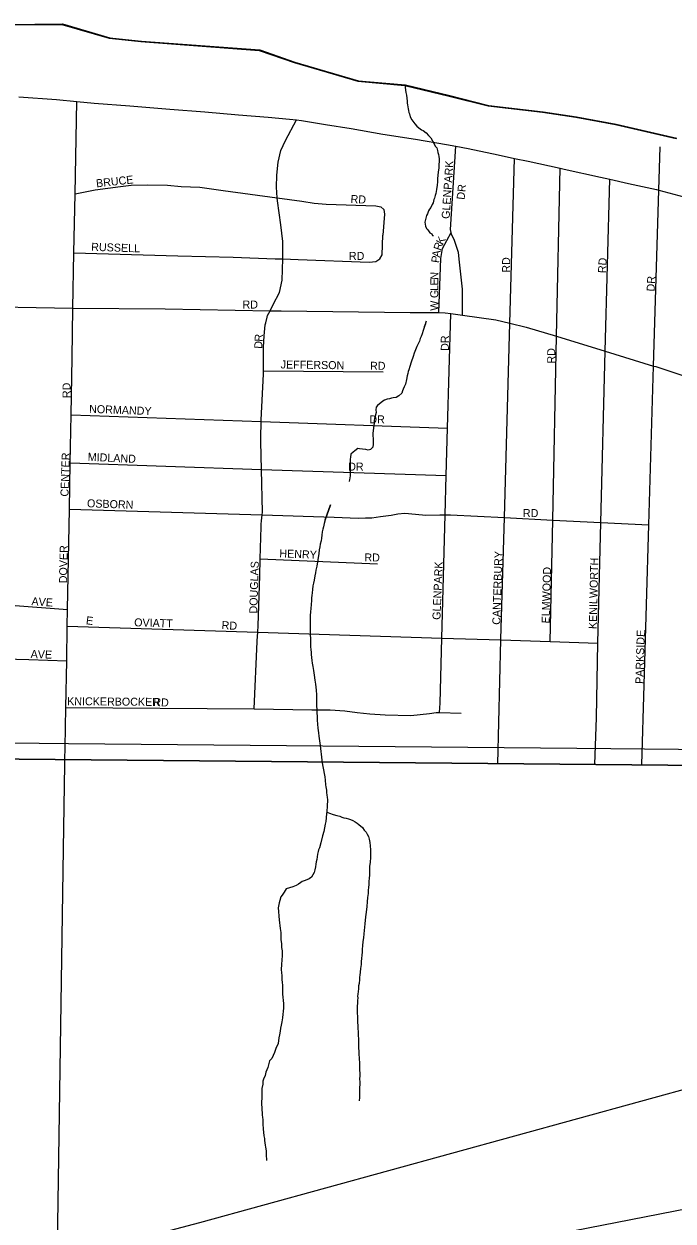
# Model space of a CAD drawing. Extents: x 2010165 to 2382125, y 1060529 to 1407316.
# Drawn here: x 2126953 to 2131007, y 1264406 to 1271883 of the extents above; entities that cross this region are included whole.
import ezdxf

# ---------------------------------------------------------------- set-up
doc = ezdxf.new("R2010")
doc.units = 0
for name, color, linetype in [('GM_X_City_Street', 7, 'Continuous'), ('GM_X_City_Street_Text', 7, 'Continuous'), ('GM_X_Corporation', 7, 'Continuous'), ('GM_X_County', 7, 'Continuous'), ('GM_X_Interstate_Route', 7, 'Continuous'), ('GM_X_Major_Lake', 7, 'Continuous'), ('GM_X_Major_River', 7, 'Continuous'), ('GM_X_Minor_River', 7, 'Continuous'), ('GM_X_Rail_Line', 7, 'Continuous'), ('GM_X_State_Route', 7, 'Continuous'), ('GM_X_US_Route', 7, 'Continuous')]:
    doc.layers.add(name, color=color, linetype=linetype)

msp = doc.modelspace()

# ---------------------------------------------------------------- linework, layer by layer
at = {"layer": 'GM_X_City_Street'}
for points in [[(2127210.5, 1267364.4), (2127214.9, 1267613.4), (2127220.1, 1267906), (2127224, 1268122.6), (2127225.8, 1268226.8), (2127237, 1268852.4), (2127242.1, 1269141.1), (2127247.5, 1269441.7), (2127253.8, 1269797.9), (2127259.3, 1270107.5), (2127265.6, 1270454.1), (2127272.4, 1270822), (2127283, 1271398.9)], [(2128462.9, 1270016.9), (2128471.6, 1270052.2), (2128474, 1270061.9), (2128490.2, 1270092.1), (2128510.3, 1270129.9), (2128548.7, 1270206), (2128565.1, 1270282.1), (2128569.2, 1270415.2), (2128569.8, 1270434.4), (2128570.2, 1270524.7), (2128556.7, 1270629), (2128537.3, 1270777.4), (2128535.6, 1270797.1), (2128529.7, 1270863.6), (2128532.1, 1270937.8), (2128540.4, 1271020), (2128556.8, 1271092.1), (2128587.1, 1271156.1), (2128655.5, 1271283.4)], [(2129693.1, 1270064.2), (2129692, 1270227.3), (2129672.7, 1270395.8), (2129667, 1270456), (2129643.3, 1270530.3), (2129623.5, 1270570.4), (2129621.5, 1270579.9), (2129617.6, 1270598.5), (2129650.6, 1271119.3)], [(2130813, 1267255.1), (2130856.4, 1268754.9), (2130886.2, 1269746.7), (2130919.1, 1270844.6), (2130927.3, 1271116.4)], [(2129912.6, 1267261.2), (2129932.1, 1268035.8), (2129932.2, 1268041), (2129953.6, 1268799.6), (2129987.8, 1270014), (2130016.8, 1271043.6)], [(2130240.3, 1268025.9), (2130256.1, 1268784.6), (2130280.1, 1269932.3), (2130302, 1270982.5)], [(2127272.4, 1270822), (2127397.9, 1270846.9), (2127556.1, 1270868.7), (2127622.2, 1270875.3), (2127726.4, 1270878.4), (2127850.7, 1270875.7), (2127935, 1270868.6), (2128051.3, 1270863.7), (2128197.8, 1270843.2), (2128535.6, 1270797.1), (2128689.6, 1270776), (2128765.9, 1270764.7), (2128840.2, 1270757.5), (2129151, 1270746.7), (2129183.1, 1270741), (2129201.3, 1270725.1), (2129205.6, 1270695.1), (2129195, 1270564.2)], [(2130518.7, 1267257.9), (2130528.6, 1267551.3), (2130536.7, 1268016.4), (2130556.2, 1268769.8), (2130583.9, 1269839.2), (2130611.7, 1270913.6)], [(2127265.6, 1270454.1), (2127915.1, 1270435.1), (2128259.5, 1270425.7), (2128522.7, 1270416.8), (2128569.2, 1270415.2), (2128665.8, 1270412), (2129110.1, 1270396.1), (2129150.2, 1270400), (2129176.3, 1270415.9), (2129190.4, 1270441.9), (2129195, 1270564.2)], [(2129545.1, 1270080.3), (2129552.2, 1270306.1), (2129556.7, 1270418.3), (2129567, 1270480.4), (2129621.5, 1270579.9)], [(2126064.8, 1270130.3), (2126571.4, 1270120.6), (2127259.3, 1270107.5)], [(2127259.3, 1270107.5), (2127835.5, 1270104.1), (2128490.2, 1270092.1), (2128559.8, 1270090.9), (2129366.2, 1270081.7), (2129545.1, 1270080.3), (2129584.3, 1270079.9), (2129618.9, 1270075), (2129693.1, 1270064.2), (2129900.4, 1270034.2), (2129987.8, 1270014), (2130090.6, 1269990.3), (2130280.1, 1269932.3), (2130583.9, 1269839.2), (2130886.2, 1269746.7), (2130899.1, 1269742.7), (2131245.9, 1269629.5)], [(2129547.8, 1267583), (2129552, 1267641.6), (2129563.2, 1268047.6), (2129584.3, 1268816.3), (2129591.1, 1269062.8), (2129599.2, 1269359.5), (2129618.9, 1270075)], [(2128433.5, 1269336.2), (2128434.1, 1269363.3), (2128434.8, 1269400.2), (2128435, 1269410.5), (2128450.3, 1269695.1), (2128450.1, 1269717.2), (2128449.1, 1269863.5), (2128453.4, 1269935.7), (2128459.7, 1270003.9), (2128462.9, 1270016.9)], [(2128450.1, 1269717.2), (2129197.1, 1269710.1)], [(2127247.5, 1269441.7), (2128434.8, 1269400.2), (2129599.2, 1269359.5)], [(2128435.5, 1268759.6), (2128437.4, 1268780), (2128440.8, 1268816.5), (2128442.4, 1268833.1), (2128436.3, 1269101.3), (2128432.4, 1269274.2), (2128433.5, 1269336.2)], [(2127242.1, 1269141.1), (2128436.3, 1269101.3), (2129591.1, 1269062.8)], [(2127237, 1268852.4), (2128440.8, 1268816.5), (2128890.7, 1268803.1), (2129040.8, 1268796.5), (2129086.9, 1268798.3), (2129126.9, 1268798.2), (2129181, 1268806), (2129247.1, 1268815.7), (2129289.1, 1268823.5), (2129331.2, 1268827.4), (2129399.3, 1268821.1), (2129463.3, 1268814.8), (2129551.4, 1268816.5), (2129584.3, 1268816.3), (2129597.1, 1268816.3), (2129603.5, 1268816.2)], [(2129603.5, 1268816.2), (2129617.5, 1268816.2), (2129953.6, 1268799.6), (2130256.1, 1268784.6), (2130556.2, 1268769.8), (2130856.4, 1268754.9)], [(2128410.4, 1268025.6), (2128410.6, 1268030.1), (2128413.2, 1268084.5), (2128415.1, 1268125.4), (2128426.6, 1268436.2), (2128429.1, 1268542.6), (2128433.9, 1268742.9), (2128435.5, 1268759.6)], [(2128429.1, 1268542.6), (2129161.6, 1268511.3)], [(2126514.3, 1267925.5), (2126528.8, 1268011), (2126553, 1268069), (2126609.5, 1268155), (2126647.7, 1268198.9), (2126685.9, 1268224.8), (2126730, 1268242.7), (2126782.1, 1268254.5), (2126872.2, 1268252.1), (2127225.8, 1268226.8)], [(2127224, 1268122.6), (2128413.2, 1268084.5), (2129563.2, 1268047.6), (2129932.1, 1268035.8), (2130240.3, 1268025.9), (2130536.7, 1268016.4)], [(2128390.7, 1267606.4), (2128410.4, 1268025.6)], [(2126085, 1267997.3), (2126156.1, 1267960.4), (2126206.1, 1267940.1), (2126314.2, 1267929.6), (2126514.3, 1267925.5), (2126984.7, 1267912.9), (2127220.1, 1267906)], [(2127214.9, 1267613.4), (2128390.7, 1267606.4), (2128632.9, 1267601.3), (2128751.1, 1267598.8), (2128865.2, 1267600.3), (2128957.2, 1267593.9), (2129035.2, 1267583.6), (2129113.3, 1267575.3), (2129209.4, 1267568.8), (2129369.5, 1267564.2), (2129485.7, 1267575.7), (2129527.7, 1267583.6), (2129547.8, 1267583), (2129683.9, 1267578.9)], [(2127208.7, 1267258.9), (2127209.2, 1267288.5), (2127210.5, 1267364.4)], [(2127200.4, 1266731.4), (2127208.7, 1267258.9)], [(2127161.7, 1264252), (2127200.4, 1266731.4)]]:
    msp.add_lwpolyline(points, dxfattribs=at)
at = {"layer": 'GM_X_Corporation'}
for points in [[(2126843.8, 1271877), (2127188.9, 1271880.7), (2127486.3, 1271793.8), (2127683.1, 1271772.7), (2128421.8, 1271718.1), (2128640.9, 1271642.9), (2129038.7, 1271526.4), (2129331.9, 1271499.7), (2129609.1, 1271432.8), (2129852.2, 1271371.8), (2130191.5, 1271331.3), (2130400.3, 1271300.2), (2130647.4, 1271255.2), (2131027.1, 1271166.8)], [(2113929.8, 1250070.4), (2113971.4, 1267404), (2121968.1, 1267337), (2140205.4, 1267168.3), (2140069, 1257837), (2140063.6, 1257468.8), (2140046.9, 1256760.6)], [(2140205.4, 1267168.3), (2121968.1, 1267337)]]:
    msp.add_lwpolyline(points, dxfattribs=at)
at = {"layer": 'GM_X_County'}
msp.add_lwpolyline([(2126843.8, 1271877), (2127188.9, 1271880.7), (2127486.3, 1271793.8), (2127683.1, 1271772.7), (2128421.8, 1271718.1), (2128640.9, 1271642.9), (2129038.7, 1271526.4), (2129331.9, 1271499.7), (2129609.1, 1271432.8), (2129852.2, 1271371.8), (2130191.5, 1271331.3), (2130400.3, 1271300.2), (2130647.4, 1271255.2), (2131027.1, 1271166.8)], dxfattribs=at)
at = {"layer": 'GM_X_Interstate_Route'}
msp.add_lwpolyline([(2123721.8, 1263614.6), (2124154.9, 1263579.3), (2124626.5, 1263564.9), (2124936.1, 1263593.7), (2125189.2, 1263634.2), (2125455.6, 1263691.8), (2127160.2, 1264161.9), (2128051.9, 1264396.6), (2131199.8, 1265264.4), (2131235.7, 1265273.7), (2132596.1, 1265624.7)], dxfattribs=at)
at = {"layer": 'GM_X_Major_Lake'}
msp.add_lwpolyline([(2126848, 1271879.6), (2127193.2, 1271883.2), (2127490.6, 1271796.4), (2127687.3, 1271775.2), (2128426, 1271720.6), (2128645.1, 1271645.4), (2129043, 1271528.9), (2129336.1, 1271502.3), (2129613.3, 1271435.4), (2129856.4, 1271374.3), (2130195.8, 1271333.8), (2130404.6, 1271302.7), (2130651.6, 1271257.8), (2131031.3, 1271169.3)], dxfattribs=at)
msp.add_lwpolyline([(2126848, 1271879.6), (2127193.2, 1271883.2), (2127490.6, 1271796.4), (2127687.3, 1271775.2), (2128426, 1271720.6), (2128645.1, 1271645.4), (2129043, 1271528.9), (2129336.1, 1271502.3), (2129613.3, 1271435.4), (2129856.4, 1271374.3), (2130195.8, 1271333.8), (2130404.6, 1271302.7), (2130651.6, 1271257.8), (2131031.3, 1271169.3)], dxfattribs=at)
at = {"layer": 'GM_X_Major_River'}
msp.add_lwpolyline([(2126848, 1271879.6), (2127193.2, 1271883.2), (2127490.6, 1271796.4), (2127687.3, 1271775.2), (2128426, 1271720.6), (2128645.1, 1271645.4), (2129043, 1271528.9), (2129336.1, 1271502.3), (2129613.3, 1271435.4), (2129856.4, 1271374.3), (2130195.8, 1271333.8), (2130404.6, 1271302.7), (2130651.6, 1271257.8), (2131031.3, 1271169.3)], dxfattribs=at)
at = {"layer": 'GM_X_Minor_River'}
for points in [[(2129331.8, 1271502.6), (2129339.1, 1271455.3), (2129343.1, 1271439.3), (2129345.2, 1271419.2), (2129347.3, 1271401.1), (2129347.3, 1271389.1), (2129349.4, 1271377.1), (2129351.4, 1271365.1), (2129353.5, 1271353), (2129355.5, 1271343), (2129357.6, 1271331), (2129361.6, 1271320.9), (2129365.7, 1271302.9), (2129375.8, 1271284.9), (2129393.9, 1271258.8), (2129408, 1271244.8), (2129420.1, 1271234.8), (2129436.2, 1271222.8), (2129446.2, 1271216.9), (2129464.4, 1271202.9), (2129480.5, 1271186.9), (2129494.6, 1271170.9), (2129504.7, 1271152.8), (2129514.8, 1271134.8), (2129520.8, 1271120.8), (2129530.9, 1271108.8), (2129537, 1271092.8), (2129539, 1271080.7), (2129543.1, 1271068.7), (2129545.1, 1271054.6), (2129547.2, 1271040.6), (2129547.3, 1271022.6), (2129545.3, 1271006.5), (2129543.4, 1270984.4), (2129539.4, 1270958.3), (2129535.6, 1270918.2), (2129535.6, 1270896.1), (2129533.7, 1270876), (2129529.8, 1270849.9), (2129525.9, 1270823.8), (2129521.9, 1270811.8), (2129517.9, 1270795.7), (2129514, 1270785.7), (2129512, 1270775.6), (2129508, 1270765.6), (2129502, 1270755.5), (2129494.1, 1270737.4), (2129486.1, 1270725.4), (2129480.1, 1270715.3), (2129474.1, 1270697.3), (2129468.1, 1270687.2), (2129462.2, 1270671.1), (2129456.2, 1270645), (2129458.3, 1270633), (2129460.3, 1270621), (2129466.4, 1270604.9), (2129476.5, 1270596.9), (2129488.6, 1270578.9), (2129500.6, 1270572.9), (2129504.7, 1270562.9), (2129510.7, 1270560.9)], [(2129464.4, 1270027), (2129454.5, 1269992.9), (2129460.4, 1270011), (2129454.5, 1269992.9), (2129446.5, 1269968.8), (2129440.6, 1269946.7), (2129434.6, 1269930.6), (2129428.6, 1269918.6), (2129422.7, 1269902.5), (2129414.7, 1269884.4), (2129406.7, 1269868.3), (2129398.8, 1269848.2), (2129390.8, 1269826.1), (2129384.9, 1269806.1), (2129371, 1269769.9), (2129363, 1269743.8), (2129357.1, 1269723.7), (2129353.1, 1269711.6), (2129351.1, 1269699.6), (2129347.2, 1269685.5), (2129343.2, 1269661.5), (2129335.3, 1269633.3), (2129327.3, 1269617.3), (2129321.4, 1269601.2), (2129317.4, 1269591.1), (2129313.4, 1269577.1), (2129295.4, 1269561), (2129277.4, 1269550.9), (2129259.3, 1269548.8), (2129249.3, 1269546.8), (2129235.3, 1269542.7), (2129221.3, 1269538.7), (2129205.2, 1269532.6), (2129195.2, 1269526.6), (2129161.2, 1269500.3), (2129153.2, 1269490.3), (2129151.2, 1269472.2), (2129153.3, 1269456.2), (2129147.4, 1269434.1), (2129143.4, 1269418), (2129141.4, 1269406), (2129139.5, 1269389.9), (2129137.5, 1269375.9), (2129135.6, 1269359.8), (2129133.6, 1269341.7), (2129131.7, 1269327.7), (2129131.7, 1269307.6), (2129133.8, 1269295.6), (2129133.9, 1269275.5), (2129133.9, 1269259.5), (2129132, 1269239.4), (2129118, 1269225.3), (2129103.9, 1269221.3), (2129087.9, 1269225.2), (2129067.8, 1269227.2), (2129049.7, 1269229.1), (2129037.7, 1269231.1), (2129019.7, 1269217), (2129009.7, 1269208.9), (2128995.7, 1269196.8), (2128991.7, 1269176.8), (2128989.8, 1269164.7), (2128989.8, 1269152.7), (2128989.8, 1269138.6), (2128989.9, 1269126.6), (2128989.9, 1269112.6), (2128990, 1269100.5), (2128990, 1269086.5), (2128990.1, 1269072.4), (2128990.1, 1269060.4), (2128988.2, 1269048.3), (2128986.2, 1269036.3), (2128984.2, 1269028.2), (2128984.2, 1269026.2)], [(2128868.3, 1268879.4), (2128834.5, 1268787), (2128868.3, 1268879.4), (2128834.5, 1268787), (2128828.6, 1268762.9), (2128824.7, 1268742.8), (2128820.7, 1268726.8), (2128816.7, 1268710.7), (2128812.8, 1268690.6), (2128810.9, 1268672.5), (2128808.9, 1268654.5), (2128803, 1268634.4), (2128801, 1268618.3), (2128797.1, 1268598.2), (2128795.1, 1268576.2), (2128783.4, 1268495.9), (2128775.4, 1268471.8), (2128773.5, 1268455.7), (2128769.5, 1268435.6), (2128765.6, 1268409.5), (2128761.7, 1268389.5), (2128757.7, 1268373.4), (2128755.8, 1268351.3), (2128753.8, 1268329.2), (2128751.9, 1268313.2), (2128749.9, 1268299.1), (2128750, 1268283.1), (2128746.1, 1268257), (2128744.1, 1268232.9), (2128742.2, 1268210.8), (2128740.3, 1268188.7), (2128740.4, 1268168.7), (2128740.4, 1268144.6), (2128740.5, 1268122.5), (2128740.6, 1268098.4), (2128740.7, 1268070.3), (2128742.8, 1268042.3), (2128742.9, 1268020.2), (2128743, 1267994.1), (2128745, 1267974), (2128747.1, 1267960), (2128747.1, 1267943.9), (2128749.2, 1267925.9), (2128751.3, 1267907.8), (2128753.4, 1267889.8), (2128757.4, 1267869.7), (2128761.5, 1267845.7), (2128765.6, 1267815.6), (2128769.8, 1267785.5), (2128773.9, 1267759.4), (2128778, 1267721.3), (2128780.1, 1267693.2), (2128780.2, 1267669.2), (2128780.3, 1267643.1), (2128780.4, 1267623), (2128782.4, 1267602.9), (2128782.5, 1267580.9), (2128784.6, 1267556.8), (2128784.7, 1267534.7), (2128786.8, 1267510.7), (2128788.9, 1267484.6), (2128793, 1267456.5), (2128795.1, 1267434.4), (2128799.2, 1267406.3), (2128803.3, 1267376.3), (2128813.6, 1267284), (2128817.7, 1267255.9), (2128823.9, 1267223.8), (2128828, 1267201.8), (2128832.1, 1267181.7), (2128834.1, 1267159.7), (2128836.2, 1267131.6), (2128838.3, 1267117.5), (2128840.3, 1267107.5), (2128842.4, 1267097.5), (2128842.4, 1267083.4), (2128844.5, 1267065.4), (2128846.5, 1267053.3), (2128848.6, 1267037.3), (2128848.7, 1267023.3), (2128846.7, 1267011.2), (2128846.7, 1266995.2), (2128844.8, 1266967.1), (2128842.9, 1266949), (2128839, 1266902.8), (2128835.1, 1266884.8), (2128825.2, 1266838.6), (2128817.3, 1266812.5), (2128807.4, 1266768.3), (2128799.5, 1266738.2), (2128793.5, 1266724.1), (2128791.5, 1266714.1), (2128787.6, 1266698), (2128783.6, 1266681.9), (2128781.7, 1266663.9), (2128777.7, 1266649.8), (2128775.7, 1266635.8), (2128773.8, 1266617.7), (2128769.8, 1266599.6), (2128765.9, 1266583.6), (2128749.9, 1266553.4)], [(2128844, 1266959.6), (2128850.9, 1266959.1), (2128860.9, 1266953.1), (2128885, 1266945.1), (2128907.1, 1266939.2), (2128925.2, 1266935.2), (2128939.3, 1266929.2), (2128951.3, 1266925.3), (2128965.4, 1266923.3), (2128979.4, 1266919.3), (2128993.5, 1266913.3), (2129007.6, 1266907.4), (2129021.6, 1266899.4), (2129033.7, 1266891.4), (2129045.8, 1266883.4), (2129067.9, 1266863.4), (2129078, 1266847.4), (2129090.1, 1266835.4), (2129096.2, 1266823.4), (2129104.2, 1266807.4), (2129110.3, 1266791.3), (2129114.4, 1266771.3), (2129116.5, 1266749.2), (2129116.6, 1266725.1), (2129116.6, 1266703.1), (2129116.7, 1266677), (2129114.8, 1266646.9), (2129110.9, 1266620.8), (2129111, 1266600.7), (2129111, 1266582.6), (2129111.1, 1266566.6), (2129109.1, 1266548.5), (2129107.2, 1266526.4), (2129107.3, 1266508.4), (2129105.3, 1266490.3), (2129103.4, 1266472.3), (2129103.5, 1266452.2), (2129099.5, 1266428.1), (2129097.6, 1266400), (2129093.7, 1266371.9), (2129089.8, 1266335.8), (2129085.9, 1266305.7), (2129082, 1266263.5), (2129076.2, 1266199.3), (2129074.3, 1266175.2), (2129070.4, 1266153.1), (2129068.5, 1266125), (2129066.5, 1266104.9), (2129066.6, 1266084.9), (2129062.7, 1266066.8), (2129060.7, 1266046.7), (2129058.8, 1266026.7), (2129058.8, 1266008.6), (2129054.9, 1265984.5), (2129053, 1265960.4), (2129051, 1265942.4), (2129049.1, 1265930.3), (2129049.1, 1265914.3), (2129047.2, 1265890.2), (2129043.2, 1265876.1), (2129043.3, 1265856.1), (2129041.4, 1265840), (2129039.4, 1265823.9), (2129037.4, 1265811.9), (2129037.5, 1265799.8), (2129035.5, 1265783.8), (2129035.6, 1265765.7), (2129033.6, 1265749.7), (2129033.7, 1265731.6), (2129033.8, 1265705.5), (2129035.9, 1265683.5), (2129036, 1265659.4), (2129038.1, 1265615.2), (2129040.2, 1265581.1), (2129042.4, 1265527), (2129042.5, 1265502.9), (2129044.7, 1265450.7), (2129046.8, 1265422.6), (2129048.9, 1265392.6), (2129049, 1265372.5), (2129049.1, 1265348.4), (2129051.1, 1265330.3), (2129051.2, 1265314.3), (2129049.3, 1265294.2), (2129051.3, 1265274.2), (2129051.4, 1265258.1), (2129049.4, 1265242.1), (2129049.5, 1265220), (2129049.6, 1265195.9), (2129049.7, 1265177.8), (2129047.7, 1265157.8), (2129047.7, 1265157.8)], [(2128749.9, 1266553.4), (2128733.9, 1266543.3), (2128709.9, 1266533.2), (2128691.8, 1266527.1), (2128681.8, 1266521.1), (2128667.8, 1266511), (2128653.8, 1266502.9), (2128631.7, 1266494.8), (2128611.7, 1266486.8), (2128591.7, 1266480.7), (2128577.7, 1266460.6), (2128565.7, 1266442.5), (2128557.7, 1266430.4), (2128551.8, 1266408.3), (2128547.8, 1266394.2), (2128543.9, 1266372.2), (2128541.9, 1266362.1), (2128542, 1266340.1), (2128544.1, 1266310), (2128546.2, 1266287.9), (2128554.4, 1266233.7), (2128558.5, 1266207.7), (2128558.6, 1266165.5), (2128562.7, 1266137.5), (2128562.8, 1266115.4), (2128564.9, 1266093.3), (2128565, 1266063.2), (2128563.1, 1266037.1), (2128561.2, 1266009), (2128559.3, 1265976.9), (2128561.4, 1265956.9), (2128563.4, 1265940.8), (2128563.5, 1265926.8), (2128563.5, 1265914.7), (2128565.6, 1265896.7), (2128567.6, 1265878.6), (2128567.7, 1265852.5), (2128567.8, 1265824.4), (2128574.1, 1265764.3), (2128574.2, 1265738.2), (2128572.2, 1265716.1), (2128570.3, 1265698), (2128568.3, 1265676), (2128564.4, 1265649.9), (2128560.5, 1265629.8), (2128556.5, 1265611.7), (2128552.6, 1265591.6), (2128548.6, 1265569.6), (2128544.7, 1265551.5), (2128540.8, 1265515.3), (2128526.9, 1265483.2), (2128518.9, 1265459.1), (2128501, 1265420.9), (2128487, 1265406.8), (2128477.1, 1265364.6), (2128463.2, 1265336.5), (2128459.2, 1265316.4), (2128449.3, 1265292.3), (2128445.3, 1265280.3), (2128445.4, 1265262.2), (2128439.4, 1265234.1), (2128439.5, 1265206), (2128439.6, 1265177.9), (2128437.7, 1265145.8), (2128437.8, 1265129.8), (2128439.8, 1265119.7), (2128439.9, 1265101.7), (2128442, 1265081.6), (2128442, 1265069.6), (2128444.1, 1265053.5), (2128446.1, 1265041.5), (2128446.2, 1265011.4), (2128448.3, 1264983.3), (2128450.5, 1264939.2), (2128454.6, 1264921.1), (2128456.6, 1264909.1), (2128458.7, 1264895.1), (2128460.7, 1264881), (2128462.8, 1264867), (2128464.8, 1264856.9), (2128466.9, 1264842.9), (2128466.9, 1264826.9), (2128467, 1264812.8), (2128469.1, 1264792.8), (2128469.1, 1264784.7)]]:
    msp.add_lwpolyline(points, dxfattribs=at)
at = {"layer": 'GM_X_Rail_Line'}
msp.add_lwpolyline([(2113972.9, 1267502.1), (2117240.2, 1267485.7), (2117936.8, 1267482.1), (2118637, 1267476.4), (2119207.2, 1267469.2), (2120788.3, 1267454.9), (2122004.3, 1267442.8), (2123412.6, 1267429.2), (2125388.1, 1267409.2), (2126127.6, 1267400.6), (2127231.4, 1267389.9), (2130406.6, 1267359.9), (2132736.5, 1267337.1), (2134810.6, 1267317.8), (2139871.2, 1267271.3), (2143552.9, 1267237)], dxfattribs=at)
at = {"layer": 'GM_X_State_Route'}
msp.add_lwpolyline([(2126822.4, 1263597.8), (2127144.9, 1263671.8), (2127481.4, 1263741.9), (2127767.9, 1263804), (2128048.4, 1263864), (2128336.9, 1263926.1), (2128579.3, 1263978.1), (2128813.7, 1264026.2), (2129847.8, 1264241.5), (2131820.6, 1264626.4), (2132584.5, 1264744.1), (2132684.6, 1264758)], dxfattribs=at)
at = {"layer": 'GM_X_US_Route'}
msp.add_lwpolyline([(2126922, 1271429), (2127156.4, 1271410.9), (2127283, 1271398.9), (2127390.8, 1271388.8), (2127615.1, 1271372.7), (2127863.5, 1271350.5), (2128083.9, 1271334.4), (2128292.2, 1271316.4), (2128478.5, 1271300.2), (2128610.7, 1271288.2), (2128655.5, 1271283.4), (2128686.9, 1271280.1), (2128837.1, 1271256.1), (2128997.3, 1271230), (2129193.7, 1271195.8), (2129398, 1271163.7), (2129592.3, 1271129.6), (2129650.6, 1271119.3), (2129728.5, 1271105.5), (2129914.8, 1271065.4), (2130016.8, 1271043.6), (2130103.1, 1271025.2), (2130302, 1270982.5), (2130327.5, 1270977.1), (2130553.8, 1270926.9), (2130611.7, 1270913.6), (2130728.1, 1270886.8), (2130904.4, 1270848.6), (2130919.1, 1270844.6), (2131074.7, 1270802.5)], dxfattribs=at)

# ---------------------------------------------------------------- texts
at = {"layer": 'GM_X_City_Street_Text'}
for s, rotation, p in [('GLENPARK', 86.13525, (2129611.3, 1270664.5)), ('BRUCE', 6.20507, (2127406.3, 1270862.4)), ('DR', 83.98889, (2129704.8, 1270783.6)), ('RD', 356.98872, (2128992, 1270765.7)), ('K', 62.38905, (2129568.6, 1270499.5)), ('RUSSELL', 358.09188, (2127372.6, 1270466.5)), ('R', 70.96211, (2129556.4, 1270463.9)), ('RD', 0.00001, (2128982.7, 1270409.3)), ('P', 81.56651, (2129545.4, 1270388)), ('A', 81.56541, (2129550.6, 1270422.8)), ('RD', 90, (2129989.7, 1270329.5)), ('RD', 86.98901, (2130588.1, 1270325.6)), ('E', 89.95901, (2129541, 1270250.3)), ('N', 88.29474, (2129541, 1270285.1)), ('DR', 86.98901, (2130891.7, 1270211.2)), ('G', 89.95627, (2129540.9, 1270171.1)), ('L', 89.95901, (2129540.9, 1270215.1)), ('RD', 0.00001, (2128318.3, 1270105.7)), ('W', 90, (2129540.9, 1270091.9)), ('D', 87.32201, (2128440.9, 1269853.7)), ('R', 86.65849, (2128442.9, 1269897.5)), ('DR', 90, (2129606.9, 1269841.1)), ('RD', 90, (2130271.3, 1269761.9)), ('JEFFERSON', 359.23653, (2128556.1, 1269731.7)), ('RD', 0.00001, (2129114.7, 1269722.9)), ('RD', 90, (2127244.1, 1269546.3)), ('NORMANDY', 357.90587, (2127359.5, 1269454.5)), ('DR', 0.00001, (2129110.3, 1269388.5)), ('CENTER', 88.20944, (2127230.9, 1268930.6)), ('MIDLAND', 357.39887, (2127350.7, 1269155.1)), ('DR', 0.00001, (2128978.3, 1269093.5)), ('OSBORN', 357.95571, (2127346.3, 1268864.9)), ('RD', 0.00001, (2130069.5, 1268803.3)), ('DOVER', 88.80717, (2127222.1, 1268389.3)), ('HENRY', 357.61074, (2128547.5, 1268552.3)), ('RD', 0.00001, (2129079.5, 1268525.9)), ('CANTERBURY', 88.1719, (2129928.1, 1268129.8)), ('KENILWORTH', 88.76755, (2130530.9, 1268103.3)), ('DOUGLAS', 88.26354, (2128410.1, 1268200.2)), ('GLENPARK', 87.6783, (2129554.1, 1268160.7)), ('ELMWOOD', 88.43154, (2130236.1, 1268138.6)), ('AVE', 356.05714, (2126999, 1268253.3)), ('E', 352.88003, (2127338.3, 1268134.4)), ('OVIATT', 358.14989, (2127641, 1268121.3)), ('RD', 356.98872, (2128186.8, 1268103.7)), ('PARKSIDE', 88.31464, (2130821.3, 1267760.2)), ('AVE', 358.02611, (2126994.3, 1267923.3)), ('KNICKERBOCKER', 359.51287, (2127222.8, 1267628.5)), ('RD', 356.98902, (2127760, 1267624.1))]:
    msp.add_text(s, height=50, rotation=rotation, dxfattribs=at).set_placement(p)

doc.saveas('drawing.dxf')
